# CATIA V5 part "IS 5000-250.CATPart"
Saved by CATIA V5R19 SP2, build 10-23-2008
Part number: IS 5000-250
Bounding box of the stored display mesh (mm): x -59.975 to 59.975, y -59.975 to 59.975, z 0 to 640
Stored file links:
  C:\Users\Bora\Desktop\3D Katı model\IS serisi\IS 5000\IS 5000-250.CATPart
  C:\Program Files\Dassault Systemes\B19\intel_a\reffiles\standard\MetricThickPitch.txt
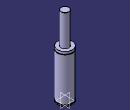
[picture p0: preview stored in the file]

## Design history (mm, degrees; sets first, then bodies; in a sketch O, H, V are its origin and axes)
Body1 (main body)
  Sketch1 on yz-plane, origin (0, 0, 0), H (0, 1, 0), V (0, 0, 1)
    point P1 (60, 367)
    point P2 (60, 362)
    point P5 (32.5, 639)
    point P7 (32.5, 639)
    point P12 (60, 362)
    point P13 (60, 367)
    arc A1 centre (60, 364.5) radius 2.5 from (60, 367) to (60, 362) ccw
    line L1 (60, 0) -> (60, 8)
    line L2 (32.5, 639) -> (32.5, 387)
    arc A2 centre (31.5, 639) radius 1 from (32.5, 639) to (31.5, 640) ccw
    line L3 (56, 13) -> (56, 8)
    line L4 (60, 13) -> (60, 362)
    line L5 (60, 367) -> (60, 387)
    line L6 (31.5, 640) -> (0, 640)
    point P15 (0, 640)
    line L7 (32.5, 387) -> (60, 387)
    line L8 (0, 0) -> (60, 0)
    line L9 (56, 13) -> (60, 13)
    line L10 (56, 8) -> (60, 8)
    coincidence: P15 V, P1 P13, P2 P12, P5 P7
    tangency: L6 A2
    horizontal: L7 H, L8 H, L9 H, L10 H
  Shaft1: profile Sketch1, axis Sketch1.V, angle 360
  Sketch2 on face of Shaft1 from Sketch1.L8, origin (0, 0, 0), H (1, 0, 0), V (0, -1, 0)
    point P1 (40, 0)
    distance P1 V = 40
  Hole1: placed by Sketch2, at (40, 0, 0) direction (0, 0, 1), diameter 8.376, depth 16, threaded "M10", thread diameter 10, thread depth 16, pitch 1.5
  CircPattern1: of Hole1, instances 4, angular step 90, axis from xy-plane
